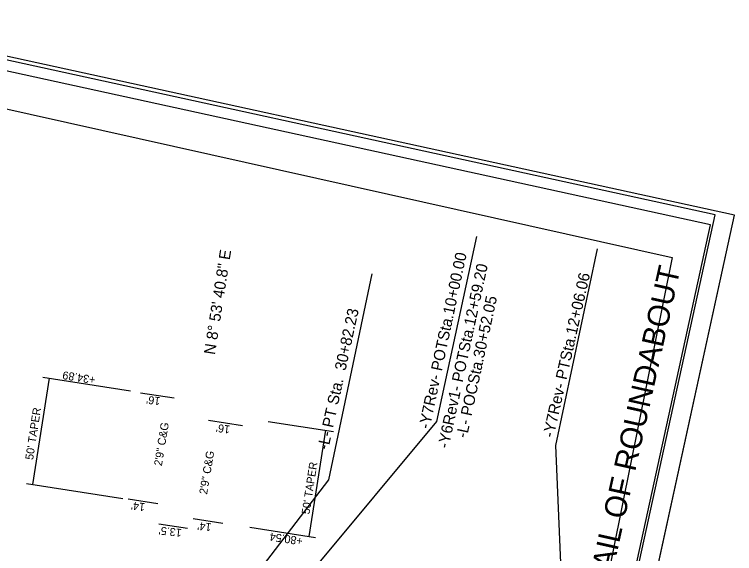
# Model space of a CAD drawing. Extents: x 1616330 to 1616903, y 901240 to 902105.
# Drawn here: x 1616566.5 to 1616903.3, y 901740.1 to 901992.3 of the extents above; entities that cross this region are included whole.
import ezdxf

# ---------------------------------------------------------------- set-up
doc = ezdxf.new("R2010")
doc.units = 0
for name, color, linetype in [('Prop Dimension', 7, 'Continuous'), ('Prop Dimension Text', 7, 'Continuous'), ('Prop Horizontal Alignment Curve and Spiral Data', 7, 'Continuous'), ('Prop Horizontal Alignment Direction Label', 7, 'Continuous'), ('Prop Horizontal Alignment Station Label', 7, 'Continuous'), ('Sheet Border Standard 30in CELL', 7, 'Continuous'), ('Sheet Clip Boundary CELL', 7, 'Continuous'), ('Sheet Cutting Line CELL', 7, 'Continuous'), ('Sheet Plot Border Inside CELL', 7, 'Continuous'), ('Sheet Plot Border Outside CELL', 7, 'Continuous')]:
    doc.layers.add(name, color=color, linetype=linetype)

msp = doc.modelspace()

# ---------------------------------------------------------------- linework, layer by layer
at = {"layer": 'Prop Dimension'}
for p, q in [((1616582.75, 901822.13), (1616575.01, 901772.46)), ((1616579.85, 901822.58), (1616620.81, 901816.2)), ((1616685.21, 901801.94), (1616715.78, 901797.18)), ((1616711.91, 901797.78), (1616704.18, 901748.11)), ((1616572.11, 901772.92), (1616617.27, 901765.88)), ((1616676.63, 901752.4), (1616707.34, 901747.62))]:
    msp.add_line(p, q, dxfattribs=at)
at = {"layer": 'Prop Dimension Text'}
for p, q in [((1616641.24, 901812.74), (1616625.44, 901815.21)), ((1616673.15, 901799.93), (1616657.34, 901802.41)), ((1616633.51, 901763.34), (1616619.68, 901765.5)), ((1616663.97, 901754.22), (1616650.14, 901756.39)), ((1616647.4, 901751.8), (1616634.06, 901753.89))]:
    msp.add_line(p, q, dxfattribs=at)
at = {"layer": 'Prop Horizontal Alignment Curve and Spiral Data'}
for p, q in [((1616764.08, 901801.92), (1616782.67, 901888.34)), ((1616819.68, 901790.61), (1616839.21, 901882.6)), ((1616713.55, 901774.6), (1616733.75, 901870.97)), ((1616621.5, 901631), (1616764.08, 901801.92)), ((1616825.59, 901648.89), (1616819.68, 901790.61)), ((1616626.32, 901660.79), (1616713.55, 901774.6))]:
    msp.add_line(p, q, dxfattribs=at)
at = {"layer": 'Sheet Border Standard 30in CELL'}
msp.add_lwpolyline([(1616481.7, 901983.51), (1616353.74, 901397.31), (1616764.08, 901307.74), (1616892.04, 901893.94)], close=True, dxfattribs=at)
at = {"layer": 'Sheet Clip Boundary CELL'}
msp.add_lwpolyline([(1616418.32, 901636.55), (1616453.3, 901785.32), (1616537.99, 901872.41), (1616557.7, 901949.17), (1616874.13, 901878.62), (1616760.29, 901314.11), (1616376.33, 901414.34)], close=True, dxfattribs=at)
at = {"layer": 'Sheet Cutting Line CELL'}
msp.add_line((1616759.6, 901240.35), (1616903.26, 901898.45), dxfattribs=at)
at = {"layer": 'Sheet Plot Border Inside CELL'}
msp.add_lwpolyline([(1616481.77, 901988.61), (1616339.61, 901337.35), (1616751.94, 901247.34), (1616894.1, 901898.61)], close=True, dxfattribs=at)
at = {"layer": 'Sheet Plot Border Outside CELL'}
msp.add_lwpolyline([(1616473.38, 901992.29), (1616329.72, 901334.18), (1616759.6, 901240.35), (1616903.26, 901898.45)], close=True, dxfattribs=at)

# ---------------------------------------------------------------- texts
at = {"layer": 'Prop Dimension'}
for s, rotation, p in [('+34.89', 171.1031, (1616604.63, 901823.06)), ("50' TAPER", 81.2285, (1616575.23, 901783.75)), ('2\'9" C&G', 80.6837, (1616635.44, 901780.89)), ('2\'9" C&G', 80.4059, (1616656.57, 901767.6)), ("50' TAPER", 81.2285, (1616704.47, 901758.31)), ('+80.54', 171.4973, (1616701.53, 901747.63))]:
    msp.add_text(s, height=3.75, rotation=rotation, dxfattribs=at).set_placement(p)
at = {"layer": 'Prop Dimension Text'}
for s, p in [("16'", (1616634.92, 901813.17)), ("16'", (1616667.52, 901799.95)), ("14'", (1616627.79, 901763.63)), ("14'", (1616658.82, 901754.2)), ("13.5'", (1616644.89, 901751.54))]:
    msp.add_text(s, height=3.75, rotation=173.1671, dxfattribs=at).set_placement(p)
at = {"layer": 'Prop Horizontal Alignment Direction Label'}
msp.add_text('N 8%%d 53\' 40.8" E', height=5.25, rotation=81.1053, dxfattribs=at).set_placement((1616660.24, 901832.88))
at = {"layer": 'Prop Horizontal Alignment Station Label'}
for s, height, rotation, p in [('-Y7Rev- POTSta.10+00.00', 5.25, 78.0083, (1616760.6, 901798.09)), ('-Y6Rev1- POTSta.12+59.20', 5.25, 77.869, (1616769.45, 901789.02)), ('DETAIL OF ROUNDABOUT', 10.2539, 77.4185, (1616840.46, 901705.26)), ('-Y7Rev- PTSta.12+06.06', 5.25, 77.4185, (1616818.6, 901794.08)), ('-L- POCSta.30+52.05', 5.25, 77.869, (1616778.03, 901793.85)), ('-L- PT Sta.  30+82.23', 5.25, 77.6862, (1616713.23, 901788.38))]:
    msp.add_text(s, height=height, rotation=rotation, dxfattribs=at).set_placement(p)

doc.saveas('drawing.dxf')
